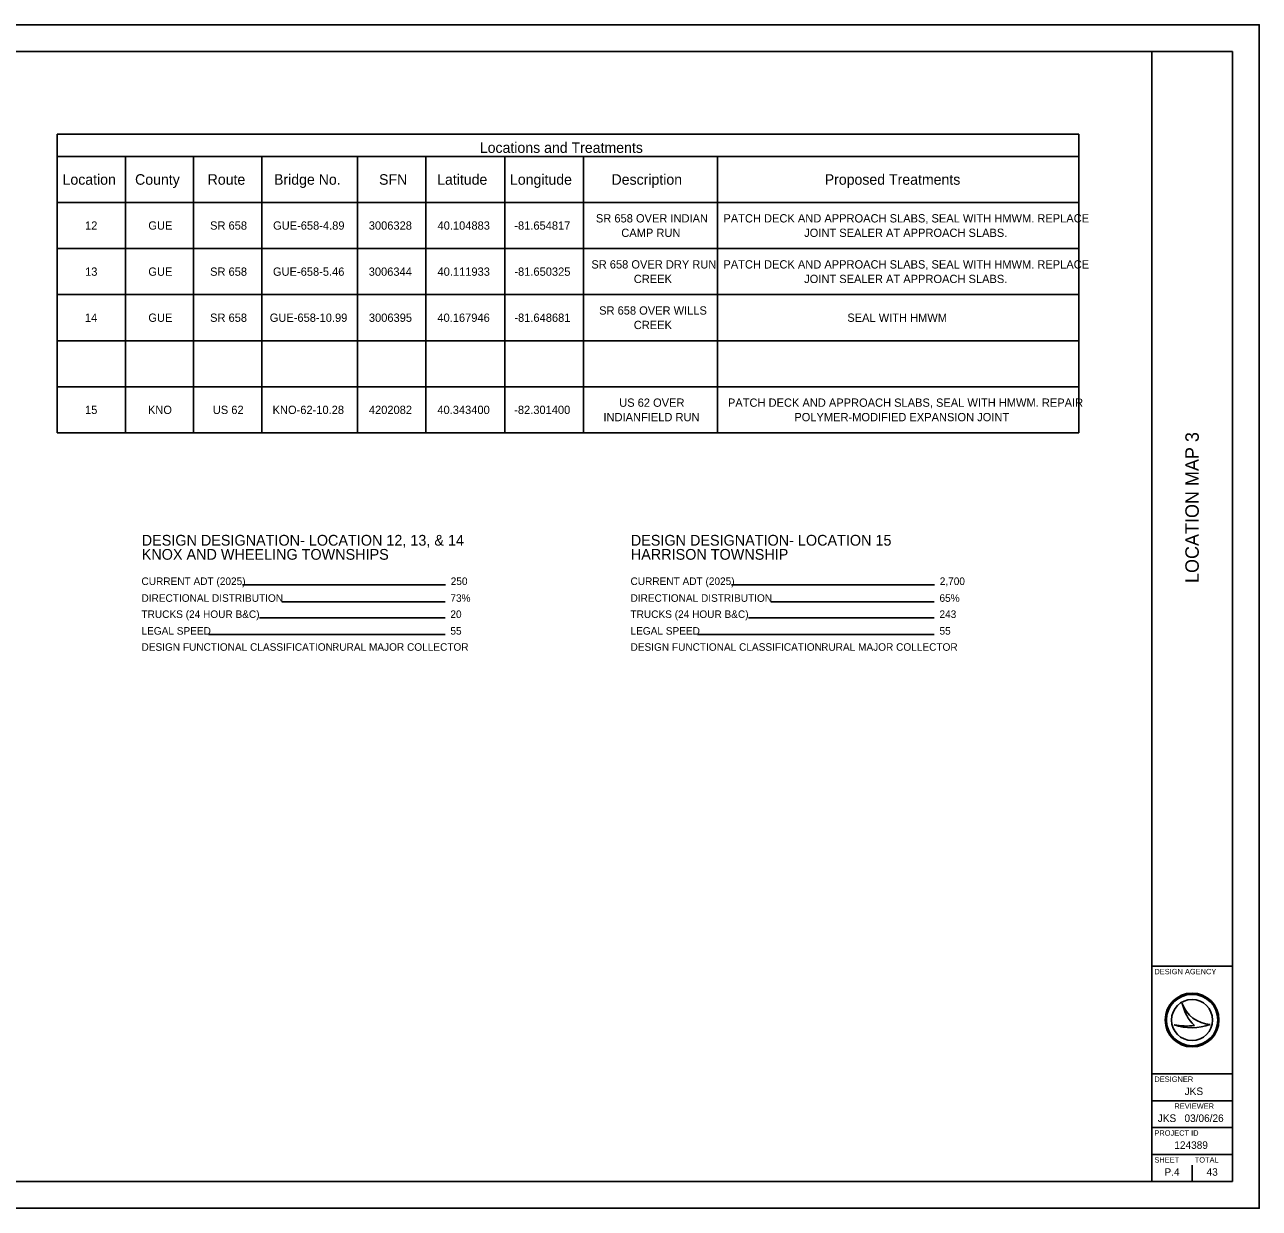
# Model space of a CAD drawing. Extents: x -12.1 to 34, y 0 to 22.
# Drawn here: x 11.05 to 34, y 0 to 22 of the extents above; entities that cross this region are included whole.
import ezdxf

# ---------------------------------------------------------------- set-up
doc = ezdxf.new("R2010")
doc.units = 0
for name, color, linetype in [('SH_Border', 7, 'Continuous'), ('SH_Cut_Line', 7, 'Continuous'), ('SH_Data', 7, 'Continuous'), ('SH_Text', 7, 'Continuous')]:
    doc.layers.add(name, color=color, linetype=linetype)

msp = doc.modelspace()

# ---------------------------------------------------------------- linework, layer by layer
at = {"layer": 'SH_Border'}
for p, q in [((32, 0.5), (32, 21.5)), ((32, 4.5), (33.5, 4.5)), ((32, 2.5), (33.5, 2.5)), ((32, 2), (33.5, 2)), ((32, 1.5), (33.5, 1.5)), ((32, 1), (33.5, 1))]:
    msp.add_line(p, q, dxfattribs=at)
msp.add_lwpolyline([(1.5, 21.5), (33.5, 21.5), (33.5, 0.5), (1.5, 0.5)], close=True, dxfattribs=at)
at = {"layer": 'SH_Cut_Line'}
msp.add_lwpolyline([(0, 0), (34, 0), (34, 22), (0, 22)], close=True, dxfattribs=at)
at = {"layer": 'SH_Data'}
for p, q in [((18.87, 11.586), (15.098, 11.586)), ((27.96, 11.586), (24.189, 11.586)), ((18.864, 11.273), (15.831, 11.273)), ((27.955, 11.273), (24.921, 11.273)), ((18.864, 10.973), (15.416, 10.973)), ((27.955, 10.973), (24.506, 10.973)), ((18.864, 10.663), (14.469, 10.663)), ((27.955, 10.663), (23.56, 10.663)), ((32.567, 3.81), (32.567, 3.81)), ((32.75, 3.5), (32.75, 3.5)), ((32.417, 3.41), (32.417, 3.41)), ((33.087, 3.419), (33.087, 3.419)), ((32.75, 0.5), (32.75, 0.8)), ((32.375, 0.675), (32.375, 0.675))]:
    msp.add_line(p, q, dxfattribs=at)
for radius in [0.5, 0.477, 0.477, 0.382]:
    msp.add_circle((32.75, 3.5), radius, dxfattribs=at)
for centre, radius, start, end in [((33.116, 3.998), 0.58, 198.9257, 198.9319), ((33.347, 3.97), 0.796, 191.6379, 191.6421), ((33.116, 3.998), 0.58, 198.9319, 267.1657), ((33.347, 3.97), 0.796, 191.6421, 226.0947), ((32.739, 4.37), 1.013, 251.4576, 290.0832), ((32.648, 4.654), 1.266, 259.4964, 259.4995), ((32.739, 4.37), 1.013, 251.4527, 251.4576), ((32.648, 4.654), 1.266, 259.4995, 276.6672)]:
    msp.add_arc(centre, radius, start, end, dxfattribs=at)
at = {"layer": 'SH_Text'}
for p, q in [((11.655, 19.963), (30.646, 19.963)), ((11.655, 19.963), (11.655, 14.413)), ((30.646, 19.963), (30.646, 14.413)), ((11.655, 19.551), (30.646, 19.551)), ((12.923, 19.551), (12.923, 14.413)), ((14.191, 19.551), (14.191, 14.413)), ((15.46, 19.551), (15.46, 14.413)), ((17.238, 19.551), (17.238, 14.413)), ((18.507, 19.551), (18.507, 14.413)), ((19.973, 19.551), (19.973, 14.413)), ((21.438, 19.551), (21.438, 14.413)), ((23.926, 19.551), (23.926, 14.413)), ((11.655, 18.695), (30.646, 18.695)), ((11.655, 17.838), (30.646, 17.838)), ((11.655, 16.982), (30.646, 16.982)), ((11.655, 16.125), (30.646, 16.125)), ((11.655, 15.269), (30.646, 15.269)), ((11.655, 14.413), (30.646, 14.413))]:
    msp.add_line(p, q, dxfattribs=at)

# ---------------------------------------------------------------- texts
at = {"layer": 'SH_Data'}
msp.add_text('LOCATION MAP 3', height=0.25, rotation=90, dxfattribs=at).set_placement((32.875, 11.623))
for s, height, p in [('DESIGN DESIGNATION- LOCATION 12, 13, & 14', 0.2, (13.227, 12.317)), ('DESIGN DESIGNATION- LOCATION 15', 0.2, (22.318, 12.317)), ('KNOX AND WHEELING TOWNSHIPS', 0.2, (13.227, 12.055)), ('HARRISON TOWNSHIP', 0.2, (22.318, 12.055)), ('DESIGN AGENCY', 0.1, (32.05, 4.35)), ('DESIGNER', 0.1, (32.05, 2.35)), ('JKS', 0.14, (32.612, 2.105)), ('REVIEWER', 0.1, (32.422, 1.85)), ('JKS', 0.14, (32.112, 1.605)), ('03/06/26', 0.14, (32.609, 1.605)), ('PROJECT ID', 0.1, (32.05, 1.35)), ('124389', 0.14, (32.42, 1.105)), ('SHEET', 0.1, (32.05, 0.85)), ('TOTAL', 0.1, (32.8, 0.85)), ('P.4', 0.14, (32.237, 0.605)), ('43', 0.14, (33.02, 0.605))]:
    msp.add_text(s, height=height, dxfattribs=at).set_placement(p)
at = {"layer": 'SH_Text'}
for s, height, p in [('Locations and Treatments', 0.196, (19.511, 19.617)), ('Location', 0.196, (11.755, 19.025)), ('County', 0.196, (13.103, 19.025)), ('Route', 0.196, (14.452, 19.025)), ('Bridge No.', 0.196, (15.686, 19.025)), ('SFN', 0.196, (17.638, 19.025)), ('Latitude', 0.196, (18.718, 19.025)), ('Longitude', 0.196, (20.072, 19.025)), ('Description', 0.196, (21.959, 19.025)), ('Proposed Treatments', 0.196, (25.922, 19.025)), ('SR 658 OVER INDIAN ', 0.154, (21.669, 18.324)), ('PATCH DECK AND APPROACH SLABS, SEAL WITH HMWM. REPLACE ', 0.154, (24.039, 18.324)), ('12', 0.154, (12.173, 18.19)), ('GUE', 0.154, (13.35, 18.19)), ('SR 658', 0.154, (14.497, 18.19)), ('GUE-658-4.89', 0.154, (15.668, 18.19)), ('3006328', 0.154, (17.447, 18.19)), ('40.104883', 0.154, (18.725, 18.19)), ('-81.654817', 0.154, (20.152, 18.19)), ('CAMP RUN', 0.154, (22.141, 18.055)), ('JOINT SEALER AT APPROACH SLABS.', 0.154, (25.54, 18.055)), ('13', 0.154, (12.174, 17.333)), ('GUE', 0.154, (13.35, 17.333)), ('SR 658', 0.154, (14.497, 17.333)), ('GUE-658-5.46', 0.154, (15.666, 17.333)), ('3006344', 0.154, (17.446, 17.333)), ('40.111933', 0.154, (18.725, 17.333)), ('-81.650325', 0.154, (20.153, 17.333)), ('SR 658 OVER DRY RUN ', 0.154, (21.584, 17.468)), ('PATCH DECK AND APPROACH SLABS, SEAL WITH HMWM. REPLACE ', 0.154, (24.039, 17.468)), ('CREEK', 0.154, (22.373, 17.198)), ('JOINT SEALER AT APPROACH SLABS.', 0.154, (25.54, 17.198)), ('SR 658 OVER WILLS ', 0.154, (21.729, 16.611)), ('14', 0.154, (12.17, 16.477)), ('GUE', 0.154, (13.35, 16.477)), ('SR 658', 0.154, (14.497, 16.477)), ('GUE-658-10.99', 0.154, (15.606, 16.477)), ('3006395', 0.154, (17.449, 16.477)), ('40.167946', 0.154, (18.722, 16.477)), ('-81.648681', 0.154, (20.153, 16.477)), ('SEAL WITH HMWM', 0.154, (26.342, 16.477)), ('CREEK', 0.154, (22.373, 16.342)), ('15', 0.154, (12.173, 14.764)), ('KNO', 0.154, (13.342, 14.764)), ('US 62', 0.154, (14.548, 14.764)), ('KNO-62-10.28', 0.154, (15.659, 14.764)), ('4202082', 0.154, (17.449, 14.764)), ('40.343400', 0.154, (18.722, 14.764)), ('-82.301400', 0.154, (20.15, 14.764)), ('US 62 OVER ', 0.154, (22.102, 14.898)), ('PATCH DECK AND APPROACH SLABS, SEAL WITH HMWM. REPAIR ', 0.154, (24.123, 14.898)), ('INDIANFIELD RUN', 0.154, (21.809, 14.629)), ('POLYMER-MODIFIED EXPANSION JOINT', 0.154, (25.357, 14.629)), ('CURRENT ADT (2025)', 0.14, (13.222, 11.586)), ('250', 0.14, (18.97, 11.586)), ('CURRENT ADT (2025)', 0.14, (22.312, 11.586)), ('2,700', 0.14, (28.06, 11.586)), ('DIRECTIONAL DISTRIBUTION', 0.14, (13.222, 11.273)), ('73%', 0.14, (18.964, 11.273)), ('DIRECTIONAL DISTRIBUTION', 0.14, (22.312, 11.273)), ('65%', 0.14, (28.055, 11.273)), ('TRUCKS (24 HOUR B&C)', 0.14, (13.222, 10.973)), ('20', 0.14, (18.964, 10.973)), ('TRUCKS (24 HOUR B&C)', 0.14, (22.312, 10.973)), ('243', 0.14, (28.055, 10.973)), ('LEGAL SPEED', 0.14, (13.222, 10.663)), ('55', 0.14, (18.964, 10.663)), ('LEGAL SPEED', 0.14, (22.312, 10.663)), ('55', 0.14, (28.055, 10.663)), ('DESIGN FUNCTIONAL CLASSIFICATION:', 0.14, (13.222, 10.363)), ('RURAL MAJOR COLLECTOR', 0.14, (16.764, 10.363)), ('DESIGN FUNCTIONAL CLASSIFICATION:', 0.14, (22.312, 10.363)), ('RURAL MAJOR COLLECTOR', 0.14, (25.855, 10.363))]:
    msp.add_text(s, height=height, dxfattribs=at).set_placement(p)

doc.saveas('drawing.dxf')
